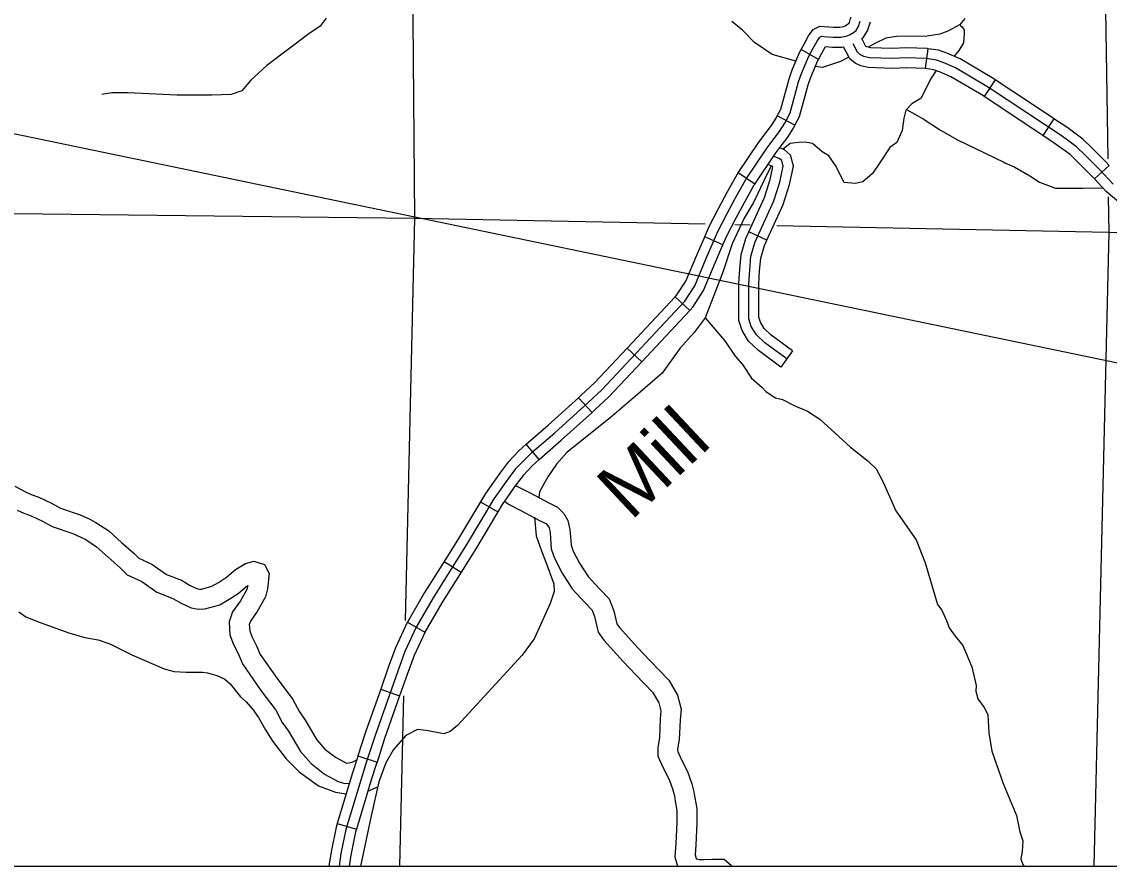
# Model space of a CAD drawing. Extents: x 0 to 3171, y 0 to 2059.
# Drawn here: x 1044.8 to 1180.8, y 254.4 to 360 of the extents above; entities that cross this region are included whole.
import ezdxf

# ---------------------------------------------------------------- set-up
doc = ezdxf.new("R2010")
doc.units = 0
for name, color, linetype in [('Default', 7, 'Continuous'), ('Level 32', 7, 'Continuous'), ('Level 35', 7, 'Continuous'), ('Level 45', 7, 'Continuous'), ('Level 46', 7, 'Continuous'), ('Level 5', 7, 'Continuous')]:
    doc.layers.add(name, color=color, linetype=linetype)

msp = doc.modelspace()

# ---------------------------------------------------------------- linework, layer by layer
at = {"layer": 'Default'}
for p, q in [((987.22, 357.79), (1387.27, 274.68)), ((1029.42, 349.02), (1387.27, 274.68)), ((1029.42, 254.41), (2119.81, 254.41))]:
    msp.add_line(p, q, dxfattribs=at)
msp.add_lwpolyline([(2119.81, 1254.61), (1029.42, 1254.61), (1029.42, 254.41), (2119.81, 254.41)], close=True, dxfattribs=at)
msp.add_lwpolyline([(2119.81, 1254.61), (1029.42, 1254.61), (1029.42, 254.41), (2119.81, 254.41)], close=True, dxfattribs=at)
msp.add_lwpolyline([(2119.81, 1254.61), (1029.42, 1254.61), (1029.42, 254.41), (2119.81, 254.41)], close=True, dxfattribs=at)
at = {"layer": 'Level 32'}
for p, q in [((1144.4, 355.32), (1142.22, 356.55)), ((1158.09, 356.66), (1157.73, 354.18)), ((1166.5, 352.77), (1165.12, 350.69)), ((1141.46, 347.1), (1139.25, 348.26)), ((1173.83, 347.91), (1172.45, 345.82)), ((1180.76, 342.07), (1178.93, 340.37)), ((1136.43, 339.72), (1134.36, 341.12)), ((1132.46, 332.13), (1130.17, 333.13)), ((1128.32, 323.94), (1126.49, 325.65)), ((1122.3, 317.52), (1120.48, 319.23)), ((1116.08, 311.16), (1114.4, 313.01)), ((1109.47, 305.3), (1107.84, 307.2)), ((1102.15, 300.01), (1104.3, 298.73)), ((1097.58, 292.53), (1099.7, 291.2)), ((1093.02, 284.95), (1095.18, 283.7)), ((1089.66, 276.57), (1092.02, 275.74)), ((1086.81, 268.21), (1089.19, 267.45)), ((1084.21, 259.78), (1086.61, 259.06))]:
    msp.add_line(p, q, dxfattribs=at)
for points in [[(1142.22, 356.55), (1142.65, 357.32), (1143.16, 358.27), (1143.73, 359.08), (1144.55, 359.47), (1145.12, 359.44), (1146.27, 359.37), (1147.07, 359.36), (1147.53, 359.46), (1147.74, 359.52), (1148.04, 359.72), (1148.18, 359.82), (1148.26, 359.96), (1148.41, 360.44), (1148.47, 360.66)], [(1108.65, 306.25), (1111.41, 308.62), (1115.59, 312.4), (1117.29, 313.99), (1127.68, 325.09), (1128.94, 327), (1130.33, 330.36), (1131.82, 333.79), (1133, 336.07), (1134.03, 338.02), (1135.31, 340.29), (1137.98, 344.25), (1138.84, 345.42), (1139.53, 346.32), (1140.18, 347.34), (1140.87, 348.64), (1141.92, 352.51), (1142.29, 353.56), (1143.18, 355.72), (1143.75, 356.72), (1144.23, 357.62), (1144.56, 358.09), (1144.8, 358.21), (1145.05, 358.2), (1146.22, 358.12), (1147.19, 358.11), (1147.85, 358.25), (1148.28, 358.38), (1148.76, 358.7), (1149.11, 358.96), (1149.41, 359.43), (1149.62, 360.1)], [(1149.81, 357.93), (1150.04, 358.1), (1150.55, 358.9), (1150.82, 359.76), (1150.89, 360.03)], [(1150.34, 356.93), (1149.81, 357.93)], [(1139.25, 348.26), (1139.7, 349.1), (1140.72, 352.88), (1141.12, 354.01), (1142.06, 356.27), (1142.22, 356.55)], [(1144.4, 355.32), (1144.84, 356.12), (1145.28, 356.93), (1146.17, 356.87), (1147.31, 356.86), (1147.52, 356.9)], [(1148.19, 355.64), (1147.52, 356.9)], [(1181.25, 339.7), (1179.45, 341.65), (1177.74, 343.34), (1176.67, 344.39), (1174.74, 345.8), (1172.79, 347.1), (1165.68, 351.82), (1161.53, 354.28), (1159.99, 354.95), (1159.14, 355.24), (1157.87, 355.42), (1155.39, 355.52), (1153.63, 355.45), (1150.79, 355.54), (1150.09, 355.7), (1149.66, 355.91), (1149.3, 356.21), (1148.74, 357.28)], [(1158.09, 356.66), (1157.99, 356.67), (1155.39, 356.77), (1153.63, 356.7), (1150.95, 356.79), (1150.34, 356.93)], [(1166.5, 352.77), (1166.35, 352.88), (1162.1, 355.39), (1160.44, 356.12), (1159.43, 356.46), (1158.09, 356.66)], [(1141.46, 347.1), (1142.04, 348.18), (1143.11, 352.14), (1143.46, 353.11), (1144.31, 355.17), (1144.4, 355.32)], [(1157.76, 354.18), (1155.4, 354.27), (1153.64, 354.2), (1150.63, 354.3), (1149.68, 354.51), (1148.97, 354.85), (1148.31, 355.4), (1148.19, 355.64)], [(1165.12, 350.69), (1165.02, 350.76), (1160.95, 353.16), (1159.53, 353.79), (1158.84, 354.02), (1157.73, 354.18)], [(1173.83, 347.91), (1173.48, 348.14), (1166.5, 352.77)], [(1172.45, 345.82), (1172.09, 346.06), (1165.12, 350.69)], [(1134.36, 341.12), (1136.96, 344.98), (1137.85, 346.18), (1138.51, 347.04), (1139.1, 347.96), (1139.25, 348.26)], [(1136.43, 339.72), (1139, 343.53), (1139.84, 344.67), (1140.56, 345.6), (1141.26, 346.71), (1141.46, 347.1)], [(1180.76, 342.07), (1180.35, 342.52), (1178.62, 344.23), (1177.48, 345.34), (1175.45, 346.83), (1173.83, 347.91)], [(1178.93, 340.37), (1178.55, 340.78), (1176.86, 342.44), (1175.86, 343.43), (1174.02, 344.78), (1172.45, 345.82)], [(1130.17, 333.13), (1130.69, 334.33), (1131.89, 336.66), (1132.94, 338.62), (1134.25, 340.95), (1134.36, 341.12)], [(1185.23, 334.2), (1183.68, 335.79), (1182.22, 337.26), (1180.39, 338.79), (1178.93, 340.37)], [(1132.46, 332.13), (1132.95, 333.26), (1134.1, 335.49), (1135.13, 337.42), (1136.37, 339.63), (1136.43, 339.72)], [(1126.49, 325.65), (1126.7, 325.87), (1127.83, 327.58), (1129.18, 330.84), (1130.17, 333.13)], [(1128.32, 323.94), (1128.67, 324.32), (1130.04, 326.41), (1131.48, 329.87), (1132.46, 332.13)], [(1120.48, 319.23), (1126.49, 325.65)], [(1122.3, 317.52), (1128.32, 323.94)], [(1114.4, 313.01), (1114.74, 313.32), (1116.4, 314.88), (1120.48, 319.23)], [(1116.08, 311.16), (1116.44, 311.48), (1118.17, 313.11), (1122.3, 317.52)], [(1107.84, 307.2), (1110.59, 309.56), (1114.4, 313.01)], [(1109.47, 305.3), (1112.24, 307.69), (1116.08, 311.16)], [(1108.65, 306.25), (1106.51, 304.11), (1105.56, 302.83), (1103.82, 300.36), (1100.46, 294.76), (1098.43, 291.53), (1096.22, 287.98), (1094.09, 284.31), (1092.67, 281.26), (1091.78, 278.83), (1088.94, 270.77), (1087.89, 267.5), (1087.32, 265.72), (1085.29, 259.02), (1084.68, 256.01), (1084.44, 254.41)], [(1107.84, 307.2), (1106.94, 306.36), (1105.56, 304.92), (1104.55, 303.57), (1102.77, 301.04), (1102.15, 300.01)], [(1109.47, 305.3), (1108.55, 304.44), (1107.46, 303.29), (1106.57, 302.1), (1104.86, 299.67), (1104.3, 298.73)], [(1102.15, 300.01), (1099.4, 295.42), (1097.58, 292.53)], [(1104.3, 298.73), (1101.53, 294.11), (1099.7, 291.2)], [(1097.58, 292.53), (1097.37, 292.2), (1095.15, 288.63), (1093.02, 284.95)], [(1099.7, 291.2), (1099.49, 290.87), (1097.29, 287.34), (1095.18, 283.7)], [(1093.02, 284.95), (1092.98, 284.89), (1091.52, 281.74), (1090.6, 279.25), (1089.66, 276.57)], [(1095.2, 283.73), (1093.83, 280.78), (1092.96, 278.41), (1092.02, 275.74)], [(1089.66, 276.57), (1087.76, 271.17), (1086.81, 268.21)], [(1092.02, 275.74), (1090.12, 270.37), (1089.19, 267.45)], [(1086.81, 268.21), (1086.7, 267.88), (1086.12, 266.09), (1084.21, 259.78)], [(1089.19, 267.45), (1089.08, 267.12), (1088.51, 265.35), (1086.61, 259.06)], [(1084.21, 259.78), (1084.08, 259.32), (1083.45, 256.23), (1083.18, 254.41)], [(1086.61, 259.06), (1086.5, 258.71), (1085.91, 255.8), (1085.71, 254.41)]]:
    msp.add_lwpolyline(points, dxfattribs=at)
at = {"layer": 'Level 35'}
for points in [[(1082.82, 360.49), (1082.1, 359.48), (1080.67, 358.52), (1075.41, 354.55), (1073.41, 352.74), (1072.27, 351.41), (1070.96, 350.94), (1068.55, 350.84), (1064.17, 350.86), (1058.01, 351.16), (1056.04, 351.13), (1054.78, 350.93)], [(1162.71, 360.43), (1162.29, 359.94), (1162.1, 359.67), (1162.17, 359.53), (1162.38, 359.4), (1162.61, 358.99), (1162.61, 358.53), (1162.53, 357.38), (1161.97, 356.45), (1161.35, 355.72)], [(1138.61, 355.93), (1136.42, 357.45), (1134.9, 358.98), (1133.57, 360.06)], [(1162.1, 359.67), (1160.58, 358.86), (1159.59, 358.5), (1158.01, 358.24), (1154.15, 358.17), (1152.81, 357.98), (1151.44, 357.3), (1150.61, 356.86)], [(1141.58, 355.1), (1138.61, 355.93)], [(1148.21, 355.61), (1147.16, 355.06), (1144.92, 354.33), (1144, 354.43)], [(1159.1, 353.94), (1158.48, 352.98), (1157.87, 351.76), (1157.26, 350.47), (1156.06, 349.77), (1155.32, 348.98), (1155.07, 347.96), (1154.88, 346.42), (1154.2, 344.93), (1153.33, 344.32), (1152.1, 342.46)], [(1155.4, 349.06), (1157.5, 347.91), (1159.66, 346.49), (1161.77, 345.27), (1167.59, 342.46)], [(1142.96, 344.95), (1142.24, 344.96), (1140.87, 344.82), (1139.98, 344.1)], [(1152.1, 342.46), (1151.17, 341.04), (1149.94, 340), (1149.02, 339.79), (1147.61, 339.92), (1146.51, 342.06), (1145.69, 343.25), (1144.86, 343.77), (1143.65, 344.79), (1142.96, 344.95)], [(1138.49, 342), (1137.53, 340.05), (1136.79, 338.45), (1136.27, 337.43), (1135.1, 335.47), (1133.59, 332.25), (1132.43, 328.73), (1131.51, 326.34), (1130.21, 323), (1128.85, 321.16), (1127.05, 319.17)], [(1167.59, 342.46), (1167.71, 342.4), (1168.95, 341.85), (1170.85, 340.76), (1172.04, 339.96), (1174.03, 339.24), (1177.45, 339.24), (1179.96, 339.26)], [(1130.21, 323), (1132.68, 320.11), (1134, 318.21), (1134.88, 317.16), (1136.01, 315.45), (1137.34, 314.3), (1137.83, 313.79), (1139.04, 313), (1139.89, 312.8), (1141.36, 312.02), (1143.03, 311.33), (1144.56, 310.35), (1148.4, 306.82), (1150.63, 305.08), (1151.62, 304.1), (1152.51, 302.44), (1154.07, 298.88), (1156.62, 295.23), (1157.76, 292.38), (1159.29, 287.15), (1159.82, 286.43), (1160.42, 285.13), (1160.75, 284.22), (1161.49, 283.18), (1162.45, 282.03), (1163.59, 279.35), (1164.14, 277.04), (1164.08, 276.29), (1164.33, 275.34), (1165.12, 274.25), (1165.57, 273.41), (1165.7, 271.11), (1166.08, 268.81), (1167.5, 264.75), (1169.15, 260.76), (1169.58, 258.7), (1169.96, 257.6), (1169.86, 256.25), (1169.69, 255.35), (1169.97, 254.62), (1170.15, 254.41)], [(1127.05, 319.17), (1124.84, 316.07), (1121.8, 313.45), (1118.61, 310.69), (1112.93, 306.14), (1111.64, 304.69), (1110.55, 303.11), (1109.51, 301.23), (1109.42, 300.54)], [(1108.88, 298.08), (1109.08, 295.75), (1109.79, 293.72), (1110.25, 292.56), (1111.3, 289.75), (1111.33, 288.78), (1110.86, 287.29)], [(1110.86, 287.29), (1108.83, 282.85), (1107.34, 280.81), (1099.26, 272.03), (1098.32, 271.27), (1097.55, 270.99), (1095.32, 271.41), (1094.27, 271.5), (1092.8, 270.76), (1091.24, 269.02), (1090.29, 267.36), (1089.43, 264.98), (1088.48, 260.7), (1087.11, 254.41)], [(1044.4, 286.24), (1045.29, 285.6), (1047.07, 284.88), (1050.65, 283.61), (1052.65, 283.02), (1054.3, 282.73), (1055.77, 282.23), (1058.51, 280.87), (1062.57, 279.09), (1063.81, 278.76), (1065.34, 278.68), (1067.38, 278.69), (1068.01, 278.62), (1069.18, 278.27), (1070.14, 277.8), (1070.84, 277.21), (1072.13, 275.62), (1072.83, 274.98), (1073.66, 274), (1074.36, 273.02), (1075.26, 271.48), (1076.15, 270.02), (1077.84, 267.83), (1079.45, 266.24), (1081.88, 264.47), (1084, 263.66), (1085.33, 263.47)], [(1088.04, 263.8), (1089.29, 264.34)]]:
    msp.add_lwpolyline(points, dxfattribs=at)
at = {"layer": 'Level 45'}
for p, q in [((1137.95, 332.71), (1135.68, 333.75)), ((1141.17, 318.87), (1139.69, 316.85))]:
    msp.add_line(p, q, dxfattribs=at)
for points in [[(1141.1, 341.2), (1141.27, 342.01), (1140.92, 343.35), (1140.17, 344.02), (1139.55, 344.27)], [(1140.43, 317.86), (1137.68, 319.87), (1136.64, 320.86), (1135.99, 321.93), (1135.69, 322.88), (1135.69, 324.05), (1135.68, 327.24), (1135.8, 328.98), (1135.95, 330.7), (1136.48, 332.5), (1138.82, 337.62), (1139.58, 339.99), (1139.99, 341.98), (1139.8, 342.67), (1139.5, 342.94), (1138.74, 343.24)], [(1135.68, 333.75), (1137.66, 338.07), (1138.37, 340.31), (1138.65, 341.7)], [(1138.65, 341.7), (1138.7, 341.92), (1138.08, 342.16)], [(1137.95, 332.71), (1139.99, 337.17), (1140.79, 339.67), (1141.1, 341.2)], [(1134.44, 324.59), (1134.43, 327.28), (1134.55, 329.08), (1134.72, 330.93), (1135.31, 332.94), (1135.68, 333.75)], [(1136.94, 324.6), (1136.93, 327.2), (1137.04, 328.89), (1137.19, 330.46), (1137.66, 332.07), (1137.95, 332.71)], [(1139.69, 316.85), (1136.88, 318.91), (1135.66, 320.07), (1134.84, 321.41), (1134.44, 322.69), (1134.44, 324.05), (1134.44, 324.59)], [(1141.17, 318.87), (1138.49, 320.83), (1137.62, 321.66), (1137.13, 322.45), (1136.94, 323.07), (1136.94, 324.05), (1136.94, 324.6)]]:
    msp.add_lwpolyline(points, dxfattribs=at)
at = {"layer": 'Level 46'}
for points in [[(1043.88, 301.96), (1045.31, 301.18), (1045.95, 300.9), (1046.88, 300.56), (1048.48, 299.81), (1049.59, 299.2), (1052.05, 298.35), (1053.26, 297.84), (1054.04, 297.42), (1055.67, 296.35), (1057.24, 294.92), (1058.77, 293.57), (1059.39, 292.95), (1061.02, 292.2), (1062.85, 290.9), (1064.74, 290.18), (1065.84, 289.53), (1066.73, 289.13), (1067.03, 289.06), (1067.25, 289.08), (1068.55, 289.43), (1069.38, 289.92), (1070.35, 290.55), (1071.51, 291.53), (1072.75, 292.26), (1073.78, 292.55), (1075.1, 292.15), (1075.72, 291.02), (1075.5, 289.11), (1075.26, 288.1), (1074.2, 286.26), (1073.36, 285.08), (1073.22, 284.66), (1073.27, 283.86), (1073.53, 283.13), (1074.13, 281.99), (1074.56, 280.91), (1076.69, 277.88), (1078.67, 275.27), (1079.48, 273.72), (1080.22, 272.67), (1081.67, 270.23), (1082.68, 269.07), (1083.99, 268.05), (1085.28, 267.35), (1085.39, 267.32), (1086.09, 267.43), (1086.65, 267.73)], [(1106.53, 302.04), (1108.34, 301.12), (1110.68, 299.87), (1111.76, 299.32), (1112.55, 298.55), (1113.06, 297.67), (1113.32, 296.53), (1113.39, 295.6), (1113.46, 294.61), (1113.69, 293.92), (1114.5, 292.32), (1115.6, 290.65), (1117, 289.1), (1118.23, 287.84), (1118.81, 286.37), (1119.18, 284.72), (1119.5, 284.27), (1121.8, 281.74), (1123.32, 280.14), (1125.69, 277.67), (1126.79, 275.8), (1127.21, 274.04), (1127.09, 272.69), (1126.99, 270.27), (1126.79, 269.06), (1126.8, 268.75), (1127.23, 267.79), (1128.01, 266.25), (1128.57, 264.71), (1128.83, 263.71), (1128.94, 262.95), (1129.19, 261.62), (1129.17, 259.81), (1129.05, 257.1)], [(1105.16, 300.09), (1105.63, 299.69), (1107.18, 298.9), (1109.52, 297.65), (1110.3, 297.26), (1110.56, 297), (1110.7, 296.75), (1110.84, 296.15), (1110.9, 295.42), (1110.99, 294.13), (1111.37, 292.95), (1112.34, 291.06), (1113.61, 289.12), (1115.18, 287.38), (1116.09, 286.45), (1116.41, 285.64), (1116.85, 283.68), (1117.54, 282.7), (1119.97, 280.04), (1121.51, 278.41), (1123.68, 276.15), (1124.45, 274.86), (1124.68, 273.86), (1124.59, 272.85), (1124.5, 270.52), (1124.29, 269.22), (1124.32, 268.19), (1124.97, 266.72), (1125.71, 265.25), (1126.18, 263.95), (1126.38, 263.21), (1126.48, 262.54), (1126.69, 261.4), (1126.67, 259.88), (1126.55, 257.27)], [(1044.21, 298.94), (1045.03, 298.58), (1045.92, 298.25), (1047.35, 297.58), (1048.57, 296.91), (1051.14, 296.02), (1052.17, 295.58), (1052.76, 295.27), (1054.13, 294.37), (1055.58, 293.05), (1057.07, 291.74), (1057.95, 290.87), (1059.76, 290.03), (1061.66, 288.68), (1063.65, 287.92), (1064.7, 287.3), (1065.94, 286.75), (1066.83, 286.55), (1067.66, 286.6), (1069.52, 287.1), (1070.7, 287.8), (1071.84, 288.54), (1072.96, 289.48), (1073.03, 289.52), (1072.91, 289.03), (1072.1, 287.61), (1071.11, 286.23), (1070.7, 285), (1070.79, 283.37), (1071.23, 282.13), (1071.86, 280.94), (1072.35, 279.71), (1074.67, 276.4), (1076.55, 273.93), (1077.34, 272.41), (1078.13, 271.31), (1079.64, 268.76), (1080.96, 267.25), (1082.61, 265.95), (1084.33, 265.03), (1085.16, 264.78), (1085.74, 264.82)], [(1126.55, 257.27), (1126.44, 255.59), (1126.78, 254.41)], [(1129.05, 257.1), (1128.97, 255.86), (1129.1, 255.38), (1129.13, 255.34), (1129.51, 255.26), (1130.12, 255.24), (1131.15, 255.32), (1131.75, 255.32), (1132.62, 255.32), (1133.51, 254.5), (1133.55, 254.41)]]:
    msp.add_lwpolyline(points, dxfattribs=at)
at = {"layer": 'Level 5'}
for points in [[(1179.73, 398.78), (1180.57, 342.9)], [(1093.6, 370.32), (1093.9, 335.47)], [(1180.64, 338.13), (1180.71, 333.72)], [(1029.42, 336.22), (1093.9, 335.47)], [(1093.9, 335.47), (1092.72, 285.14)], [(1093.9, 335.47), (1130.24, 334.74)], [(1133.92, 334.66), (1135.84, 334.62)], [(1139.18, 334.56), (1180.71, 333.72)], [(1180.71, 333.72), (1178.85, 254.41)], [(1180.71, 333.72), (1185.13, 333.61)], [(1092.5, 275.73), (1092, 254.41)]]:
    msp.add_lwpolyline(points, dxfattribs=at)

# ---------------------------------------------------------------- texts
at = {"layer": 'Level 35'}
msp.add_text('Mill', height=7.04, rotation=43.1656, dxfattribs=at).set_placement((1120.93, 297.52))

doc.saveas('drawing.dxf')
